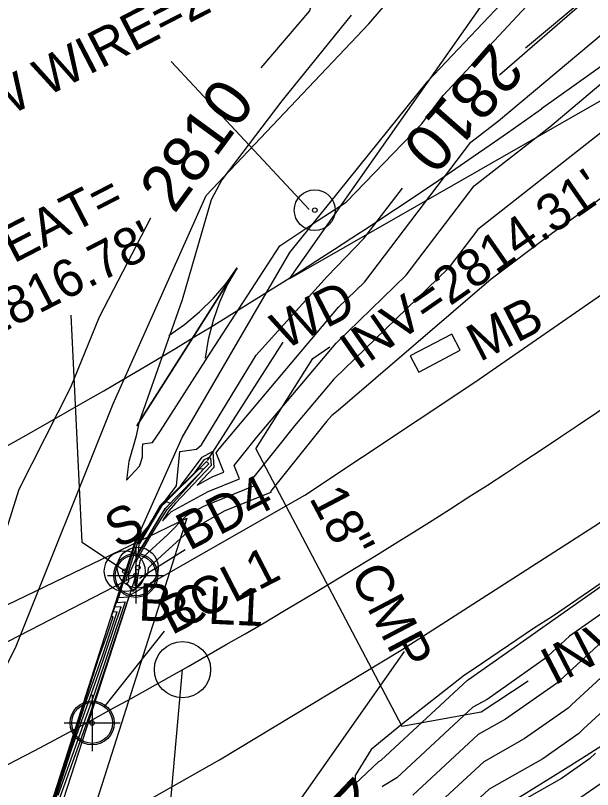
# Model space of a CAD drawing. Extents: x 1284446 to 1285480, y 969739 to 970628.
# Drawn here: x 1284903.3 to 1284964.9, y 970190.8 to 970273.5 of the extents above; entities that cross this region are included whole.
import ezdxf

# ---------------------------------------------------------------- set-up
doc = ezdxf.new("R2010")
doc.units = 0
for name, color, linetype in [('Cogo Default Point CELL', 7, 'Continuous'), ('Default', 7, 'Continuous'), ('Exist Horizontal Alignment', 7, 'Continuous'), ('Exist Horizontal Alignment Point', 7, 'Continuous'), ('Exist Hydro Jurisdictional Stream or Body of Water', 7, 'Continuous'), ('Exist Hydro River Flow Arrow CELL', 7, 'Continuous'), ('Exist Other Culture Fence Line', 7, 'Continuous'), ('Exist Other Culture Located Object CELL', 7, 'Continuous'), ('Exist Other Culture Located Object Leader', 7, 'Continuous'), ('Exist Other Culture Located Object Text', 7, 'Continuous'), ('Exist Other Culture Sign CELL', 7, 'Continuous'), ('Exist Other Culture Sign Text', 7, 'Continuous'), ('Exist Right of Way Line', 7, 'Continuous'), ('Exist Roads EOP', 7, 'Continuous'), ('Exist Roads Soil', 7, 'Continuous'), ('Exist Structure Major Bridge WW', 7, 'Continuous'), ('Exist Structure Major Bridge WW Leader', 7, 'Continuous'), ('Exist Structure Major Bridge WW Text', 7, 'Continuous'), ('Exist Structure Major Deck Tunnel Box Culvert', 7, 'Continuous'), ('Exist Structure Minor Head and End Wall', 7, 'Continuous'), ('Exist Structure Minor Pipes CMP 18 Inch', 7, 'Continuous'), ('Exist Structure Minor Pipes CMP 18 Inch Invert', 7, 'Continuous'), ('Exist Structure Minor Pipes CMP 18 Inch Leader', 7, 'Continuous'), ('Exist Structure Minor Pipes CMP 18 Inch Text', 7, 'Continuous'), ('Exist Utilities Other Located Object CELL', 7, 'Continuous'), ('Exist Utilities Other Located Object Leader', 7, 'Continuous'), ('Exist Utilities Other Located Object Text', 7, 'Continuous'), ('Exist Vegetation Woods Line', 7, 'Continuous')]:
    doc.layers.add(name, color=color, linetype=linetype)

msp = doc.modelspace()

# ---------------------------------------------------------------- linework, layer by layer
at = {"layer": 'Cogo Default Point CELL'}
for points in [[(1284916.141, 970216.687), (1284916.141, 970213.687)], [(1284913.141, 970213.687), (1284916.141, 970213.687)], [(1284916.141, 970213.687), (1284919.141, 970213.687)], [(1284916.141, 970213.687), (1284916.141, 970210.687)], [(1284911.49, 970200.942), (1284911.49, 970197.942)], [(1284908.49, 970197.942), (1284911.49, 970197.942)], [(1284911.49, 970197.942), (1284914.49, 970197.942)], [(1284911.49, 970197.942), (1284911.49, 970194.942)]]:
    msp.add_lwpolyline(points, dxfattribs=at)
for centre in [(1284916.141, 970213.687), (1284911.49, 970197.942)]:
    msp.add_circle(centre, 2.344, dxfattribs=at)
at = {"layer": 'Default'}
for points in [[(1284993.353, 970338.772), (1284991.968, 970336.215), (1284985.772, 970331.038), (1284969.063, 970325.96), (1284962.853, 970312.438), (1284950.453, 970302.482), (1284943.379, 970292.882), (1284936.842, 970279.392), (1284935.155, 970275.904), (1284934.659, 970273.982), (1284929.481, 970267.886)], [(1284957.725, 970270.027), (1284971.01, 970281.137), (1284973.097, 970282.91), (1284979.044, 970288.111), (1284991.312, 970298.925), (1284992.311, 970299.757), (1285008.113, 970310.045), (1285009.581, 970311.09), (1285032.275, 970326.549), (1285033.302, 970327.279), (1285034.748, 970328.264), (1285037.251, 970330.357)], [(1284939.112, 970273.487), (1284931.708, 970264.363), (1284925.305, 970255.933), (1284924.194, 970253.801), (1284921.1, 970243.111), (1284916.498, 970230.101), (1284916.136, 970228.435), (1284915.413, 970225.857), (1284915.144, 970223.875), (1284916.55, 970225.358), (1284916.668, 970225.745), (1284916.846, 970226.369), (1284916.854, 970227.25), (1284916.901, 970227.74), (1284917.93, 970227.896), (1284918.794, 970229.142), (1284924.157, 970237.511), (1284931.496, 970248.884), (1284935.562, 970251.582), (1284938.58, 970253.553), (1284946.619, 970261.883), (1284948.946, 970264.937), (1284962.76, 970279.802)], [(1284904.668, 970181.092), (1284910.771, 970200.049), (1284912.626, 970205.215), (1284914.161, 970209.812), (1284913.743, 970209.785), (1284913.903, 970210.31), (1284915.567, 970215.497), (1284916.047, 970217.068), (1284916.143, 970217.509), (1284916.226, 970217.516), (1284916.548, 970217.827), (1284916.563, 970217.649), (1284917.249, 970218.486), (1284918.101, 970219.915), (1284918.819, 970221.161), (1284920.915, 970223.231), (1284923.212, 970226.318), (1284924.322, 970226.921), (1284924.346, 970226.903), (1284924.483, 970225.23), (1284922.697, 970223.343), (1284924.373, 970224.262), (1284925.544, 970224.733), (1284924.704, 970226.792), (1284925.046, 970227.221), (1284937.771, 970242.33), (1284940.54, 970245.015), (1284951.894, 970259.932), (1284954.824, 970262.237), (1284970.86, 970275.722)], [(1284904.949, 970181.621), (1284909.292, 970195.115), (1284912.185, 970203.17), (1284914.578, 970210.338), (1284913.927, 970210.296), (1284914.177, 970211.114), (1284915.353, 970214.779), (1284916.088, 970217.188), (1284916.156, 970217.499), (1284916.285, 970217.51), (1284916.512, 970217.73), (1284916.535, 970217.452), (1284917.008, 970218.03), (1284918.356, 970220.288), (1284918.845, 970221.137), (1284922.469, 970224.715), (1284923.47, 970226.062), (1284923.954, 970226.325), (1284924.125, 970226.198), (1284924.188, 970225.426), (1284920.371, 970221.392), (1284919.658, 970220.602), (1284918.997, 970219.537), (1284919.943, 970220.507), (1284923.875, 970222.664), (1284927.216, 970224.007), (1284926.641, 970225.418), (1284929.054, 970228.438), (1284937.514, 970238.483), (1284944.999, 970245.742), (1284952.253, 970255.273), (1284960.293, 970261.595), (1284970.061, 970269.81)], [(1284965.762, 970260.953), (1284952.612, 970250.613), (1284949.459, 970246.47), (1284937.257, 970234.636), (1284933.061, 970229.654), (1284928.578, 970224.043), (1284928.889, 970223.281), (1284923.377, 970221.067), (1284921.504, 970220.039), (1284919.571, 970218.057), (1284917.465, 970216.134), (1284916.582, 970215.249), (1284916.221, 970212.639), (1284916.118, 970212.512), (1284916.075, 970212.575), (1284916.088, 970212.583), (1284916.17, 970215.104), (1284916.366, 970215.55), (1284917.035, 970216.714), (1284918.009, 970218.333), (1284919.484, 970220.712), (1284923.419, 970225.066), (1284922.952, 970225.04), (1284922.876, 970225.068), (1284918.871, 970221.112), (1284918.611, 970220.661), (1284916.768, 970217.573), (1284916.507, 970217.255), (1284916.476, 970217.632), (1284916.344, 970217.505), (1284916.169, 970217.489), (1284916.129, 970217.308), (1284915.138, 970214.062), (1284914.451, 970211.919), (1284914.111, 970210.807), (1284914.996, 970210.864), (1284911.744, 970201.125), (1284907.814, 970190.18)], [(1284971.031, 970257.751), (1284960.473, 970250.161), (1284954.062, 970245.315), (1284937.743, 970231.297), (1284937.062, 970230.771), (1284936.483, 970230.138), (1284930.515, 970222.668), (1284930.561, 970222.556), (1284925.636, 970220.577), (1284921.706, 970218.352), (1284917.667, 970214.666), (1284917.467, 970214.465), (1284917.385, 970213.872), (1284915.838, 970211.965), (1284915.195, 970212.913), (1284915.39, 970213.028), (1284915.413, 970213.738), (1284916.388, 970215.964), (1284916.527, 970216.205), (1284919.111, 970220.5), (1284919.311, 970220.822), (1284919.844, 970221.411), (1284919.78, 970221.408), (1284919.373, 970221.559), (1284918.896, 970221.088), (1284918.866, 970221.035), (1284916.528, 970217.117), (1284916.479, 970217.057), (1284916.44, 970217.535), (1284916.403, 970217.499), (1284916.182, 970217.48), (1284916.171, 970217.428), (1284914.924, 970213.344), (1284914.724, 970212.723), (1284914.295, 970211.318), (1284915.414, 970211.39), (1284911.304, 970199.08), (1284906.335, 970185.246)], [(1284904.388, 970180.562), (1284912.249, 970204.984), (1284913.067, 970207.26), (1284913.743, 970209.286), (1284913.559, 970209.275), (1284913.63, 970209.506), (1284915.782, 970216.215), (1284916.006, 970216.948), (1284916.13, 970217.518), (1284916.167, 970217.521), (1284916.584, 970217.925), (1284916.591, 970217.846), (1284917.489, 970218.942), (1284917.846, 970219.542), (1284918.793, 970221.185), (1284919.362, 970221.747), (1284920.479, 970223.249), (1284920.834, 970226.907), (1284922.623, 970227.179), (1284923.151, 970227.639), (1284928.991, 970237.213), (1284936.558, 970245.595), (1284940.464, 970249.643), (1284944.58, 970255.046)], [(1284917.725, 970251.824), (1284912.221, 970241.257), (1284909.188, 970233.769), (1284903.658, 970222.875), (1284899.099, 970208.331), (1284895.642, 970208.459), (1284895.374, 970207.464), (1284895.028, 970206.937), (1284895.408, 970206.436), (1284895.414, 970206.433), (1284896.05, 970205.718), (1284895.957, 970205.436), (1284895.886, 970205.226), (1284892.06, 970192.808), (1284892.035, 970192.791), (1284891.792, 970192.037), (1284885.68, 970173.557)], [(1285023.315, 970249.675), (1285021.084, 970248.148), (1285020.161, 970247.565), (1284997.794, 970231.936), (1284995.442, 970230.359), (1284984.499, 970222.715), (1284984.465, 970222.692), (1284962.415, 970207.193), (1284960.098, 970205.059), (1284959.965, 970204.937), (1284953.611, 970200.463), (1284952.107, 970199.612), (1284943.999, 970192.092), (1284942.465, 970191.143), (1284942.427, 970191.107)], [(1285042.653, 970246.7), (1285030.955, 970239.317), (1285026.048, 970235.957), (1285020.076, 970232.189), (1285009.58, 970224.855), (1284995.12, 970215.158), (1284990.095, 970211.647), (1284989.886, 970211.508), (1284979.764, 970204.393), (1284966.442, 970192.123), (1284965.678, 970191.419), (1284963.516, 970189.897), (1284961.431, 970188.717)], [(1284944.414, 970197.709), (1284941.239, 970195.115), (1284939.537, 970192.345), (1284939.507, 970191.4), (1284942.074, 970193.822), (1284942.31, 970193.968), (1284951.534, 970202.522), (1284951.631, 970202.576), (1284958.823, 970207.64), (1284958.83, 970207.646), (1284958.945, 970207.753), (1284982.698, 970224.449), (1284960.581, 970209.292), (1284958.577, 970208.023), (1284952.236, 970203.706), (1284951.208, 970203.06), (1284944.414, 970197.709)], [(1284965.885, 970206.633), (1284961.367, 970202.472), (1284961.108, 970202.233), (1284955.592, 970198.35), (1284952.68, 970196.702), (1284945.687, 970190.217)], [(1284969.355, 970206.073), (1284962.636, 970199.885), (1284962.25, 970199.53), (1284957.573, 970196.237), (1284953.253, 970193.792), (1284947.376, 970188.342), (1284943.247, 970185.786), (1284937.09, 970179.976), (1284936.128, 970177.527), (1284932.242, 970172.962), (1284929.781, 970166.204), (1284927.903, 970162.783), (1284926.325, 970159.414), (1284925.334, 970149.069), (1284927.213, 970144.924), (1284927.837, 970136.625), (1284928.271, 970131.323), (1284934.419, 970108.445), (1284935.987, 970105.544), (1284936.059, 970105.2), (1284928.643, 970101.235)], [(1284972.825, 970205.513), (1284963.905, 970197.298), (1284963.393, 970196.826), (1284959.554, 970194.123), (1284953.826, 970190.882), (1284949.064, 970186.466), (1284943.638, 970183.107), (1284938.697, 970178.445), (1284937.355, 970175.027), (1284934.415, 970171.573), (1284932.553, 970166.46), (1284929.796, 970161.44), (1284927.482, 970156.497), (1284926.953, 970150.975), (1284929.973, 970144.313), (1284930.37, 970139.03), (1284931.171, 970129.256), (1284934.552, 970116.671), (1284940.324, 970105.995), (1284940.368, 970105.785), (1284935.843, 970103.366)], [(1284965.173, 970194.711), (1284964.535, 970194.123), (1284961.535, 970192.01), (1284954.399, 970187.972), (1284950.753, 970184.591), (1284944.029, 970180.429), (1284940.304, 970176.914), (1284938.581, 970172.527), (1284936.587, 970170.184), (1284935.324, 970166.717), (1284931.69, 970160.098), (1284928.638, 970153.581), (1284928.571, 970152.882), (1284932.733, 970143.702), (1284932.903, 970141.436), (1284934.07, 970127.188), (1284934.685, 970124.898), (1284944.661, 970106.446), (1284944.677, 970106.37), (1284943.043, 970105.497)]]:
    msp.add_lwpolyline(points, dxfattribs=at)
at = {"layer": 'Exist Horizontal Alignment'}
msp.add_line((1284917.711, 970165.4), (1284921.129, 970203.635), dxfattribs=at)
msp.add_arc((1284607.883, 970757.202), 636.05, 292.002785, 305.452776, dxfattribs=at)
at = {"layer": 'Exist Horizontal Alignment Point'}
msp.add_circle((1284921.13, 970203.634), 3, dxfattribs=at)
at = {"layer": 'Exist Hydro Jurisdictional Stream or Body of Water'}
for points in [[(1284873.191, 970156.896), (1284883.514, 970166.483), (1284889.938, 970172.965), (1284895.436, 970190.434), (1284903.301, 970205.953), (1284913.733, 970232.003), (1284923.66, 970254.249), (1284941.007, 970272.574), (1284958.155, 970292.526), (1284979.255, 970313.173), (1284998.608, 970327.405), (1285021.767, 970343.415), (1285038.635, 970357.962), (1285060.694, 970382.427), (1285077.066, 970403.68), (1285083.989, 970417.362), (1285093.674, 970433.198), (1285120.383, 970455.771)], [(1284898.552, 970093.674), (1284891.925, 970104.571), (1284887.089, 970113.682), (1284882.059, 970129.577), (1284887.805, 970135.613), (1284894.463, 970156.081), (1284893.685, 970164.507), (1284897.372, 970171.054), (1284903.86, 970179.349), (1284904.341, 970180.602), (1284915.977, 970216.964), (1284921.108, 970228.406), (1284932.561, 970248.168), (1284947.309, 970266.45), (1284964.912, 970285.055), (1284987.353, 970303.198), (1285005.056, 970315.298), (1285028.92, 970334.487), (1285047.82, 970349.987), (1285069.692, 970374.615), (1285084.308, 970397.98), (1285093.11, 970411.535), (1285103.272, 970427.017), (1285126.728, 970448.135)]]:
    msp.add_lwpolyline(points, dxfattribs=at)
at = {"layer": 'Exist Hydro River Flow Arrow CELL'}
msp.add_line((1284921.602, 970238.095), (1284921.602, 970238.095), dxfattribs=at)
msp.add_lwpolyline([(1284919.669, 970239.318), (1284921.344, 970240.492), (1284922.939, 970241.82), (1284924.43, 970243.288), (1284925.79, 970244.853), (1284926.95, 970246.545), (1284916.254, 970229.645), (1284926.95, 970246.545), (1284925.917, 970244.772), (1284925.085, 970242.873), (1284924.397, 970240.897), (1284923.879, 970238.888), (1284923.535, 970236.872)], dxfattribs=at)
at = {"layer": 'Exist Other Culture Fence Line'}
msp.add_lwpolyline([(1285182.442, 970426.985), (1285127.532, 970386.926), (1285081.552, 970356.809), (1285037.111, 970332.557), (1285005.278, 970312.728), (1284979.015, 970288.014), (1284954.934, 970267.092)], dxfattribs=at)
at = {"layer": 'Exist Other Culture Located Object CELL'}
msp.add_lwpolyline([(1284946.328, 970235.396), (1284950.751, 970237.73), (1284949.84, 970239.456), (1284945.417, 970237.122)], close=True, dxfattribs=at)
for centre, radius in [((1284914.967, 970214.139), 2.18), ((1284916.141, 970213.687), 2.18), ((1284914.967, 970214.139), 0.24), ((1284916.141, 970213.687), 0.24), ((1284911.49, 970197.942), 2.18), ((1284911.49, 970197.942), 0.24)]:
    msp.add_circle(centre, radius, dxfattribs=at)
at = {"layer": 'Exist Other Culture Located Object Leader'}
for p, q in [((1284916.543, 970213.402), (1284921.405, 970216.473)), ((1284912.774, 970199.638), (1284919.218, 970207.744))]:
    msp.add_line(p, q, dxfattribs=at)
msp.add_lwpolyline([(1284914.967, 970214.139), (1284910.418, 970217.198), (1284909.254, 970241.471)], dxfattribs=at)
at = {"layer": 'Exist Other Culture Located Object Text'}
for p, q in [((1284864.825, 970192.389), (1284921.603, 970219.816)), ((1284921.603, 970219.816), (1284909.054, 970180.437))]:
    msp.add_line(p, q, dxfattribs=at)
at = {"layer": 'Exist Other Culture Sign CELL'}
for radius in [2.18, 0.24]:
    msp.add_circle((1284916.356, 970214.523), radius, dxfattribs=at)
at = {"layer": 'Exist Right of Way Line'}
msp.add_line((1285172.162, 970415.007), (1284959.411, 970263.517), dxfattribs=at)
for radius in [606.05, 666.05]:
    msp.add_arc((1284607.883, 970757.202), radius, 292.002785, 305.452776, dxfattribs=at)
at = {"layer": 'Exist Roads EOP'}
for points in [[(1284915.494, 970211.588), (1284915.697, 970211.691), (1284934.182, 970222.248), (1284952.291, 970234.314), (1284978.036, 970252.145), (1285001.962, 970268.988), (1285024.008, 970284.75), (1285046.433, 970300.937), (1285068.794, 970317.003), (1285091.504, 970333.21), (1285113.877, 970349.184), (1285137.455, 970366.054), (1285160.856, 970382.777), (1285183.611, 970398.866)], [(1284906.416, 970183.309), (1284909.887, 970185.394), (1284925.086, 970193.996), (1284944.45, 970205.721), (1284965.49, 970219.252), (1284989.098, 970235.634), (1285013.023, 970252.465), (1285035.596, 970268.522), (1285058.253, 970284.751), (1285080.338, 970300.375), (1285103.047, 970316.584), (1285125.598, 970332.829), (1285149.347, 970349.654), (1285172.355, 970366.089), (1285195.515, 970382.272)]]:
    msp.add_lwpolyline(points, dxfattribs=at)
at = {"layer": 'Exist Roads Soil'}
msp.add_lwpolyline([(1284944.788, 970205.561), (1284933.598, 970189.665), (1284927.061, 970176.274), (1284923.85, 970165.655), (1284922.668, 970145.93), (1284924.834, 970133.774), (1284934.499, 970104.988)], dxfattribs=at)
at = {"layer": 'Exist Structure Major Bridge WW'}
msp.add_lwpolyline([(1284923.936, 970225.594), (1284923.67, 970225.863), (1284918.9, 970221.085), (1284916.473, 970217.012), (1284916.394, 970216.072), (1284919.284, 970220.839), (1284923.936, 970225.594)], dxfattribs=at)
at = {"layer": 'Exist Structure Major Bridge WW Leader'}
msp.add_line((1284923.802, 970225.972), (1284931.862, 970238.586), dxfattribs=at)
at = {"layer": 'Exist Structure Major Deck Tunnel Box Culvert'}
msp.add_lwpolyline([(1284893.517, 970202.025), (1284916.141, 970213.687), (1284905.121, 970179.642), (1284882.421, 970167.887), (1284893.517, 970202.025)], dxfattribs=at)
at = {"layer": 'Exist Structure Minor Head and End Wall'}
for points in [[(1284916.426, 970217.497), (1284916.187, 970217.476), (1284914.838, 970213.059)], [(1284915.12, 970213.217), (1284916.426, 970217.497)]]:
    msp.add_lwpolyline(points, dxfattribs=at)
at = {"layer": 'Exist Structure Minor Pipes CMP 18 Inch'}
msp.add_line((1284928.934, 970227.194), (1284944.528, 970197.608), dxfattribs=at)
at = {"layer": 'Exist Structure Minor Pipes CMP 18 Inch Leader'}
for points in [[(1284928.934, 970227.194), (1284935.04, 970236.844), (1284936.826, 970238.087)], [(1284944.528, 970197.608), (1284952.994, 970199.122), (1284957.986, 970202.451)]]:
    msp.add_lwpolyline(points, dxfattribs=at)
at = {"layer": 'Exist Utilities Other Located Object CELL'}
for radius in [2.18, 0.24]:
    msp.add_circle((1284935.235, 970252.685), radius, dxfattribs=at)
at = {"layer": 'Exist Utilities Other Located Object Leader'}
msp.add_line((1284934.651, 970252.758), (1284919.93, 970268.563), dxfattribs=at)
at = {"layer": 'Exist Vegetation Woods Line'}
msp.add_lwpolyline([(1285171.523, 970440.57), (1285121.644, 970393.923), (1285081.626, 970356.869), (1285045.468, 970320.171), (1285013.496, 970297.408), (1284993.359, 970280.224), (1284932.548, 970245.359), (1284996.184, 970336.002), (1285054.451, 970386.33), (1285100.519, 970417.686), (1285131.323, 970449.808)], dxfattribs=at)

# ---------------------------------------------------------------- texts
at = {"layer": 'Default'}
for s, rotation, p in [('2810', 228.73317, (1284954.122, 970270.761)), ('2810', 53.79956, (1284920.261, 970252.196)), ('2820', 226.42269, (1284939.516, 970192.456))]:
    msp.add_text(s, height=5, rotation=rotation, dxfattribs=at).set_placement(p)
at = {"layer": 'Exist Other Culture Located Object Text'}
for s, rotation, p in [('SEAT=', 27.32349, (1284899.945, 970245.325)), ("2816.78'", 27.32349, (1284900.517, 970238.866)), ('MB', 27.32349, (1284952.824, 970236.439)), ('BD4', 27.32349, (1284921.836, 970216.274)), ('BCL1', 27.32349, (1284919.973, 970207.279)), ('BCL1', 357.32349, (1284916.364, 970208.894))]:
    msp.add_text(s, height=4, rotation=rotation, dxfattribs=at).set_placement(p)
at = {"layer": 'Exist Other Culture Sign Text'}
msp.add_text('S', height=4, rotation=27.32349, dxfattribs=at).set_placement((1284914.19, 970216.48))
at = {"layer": 'Exist Structure Major Bridge WW Text'}
msp.add_text('WD', height=4, rotation=27.32349, dxfattribs=at).set_placement((1284931.983, 970237.718))
at = {"layer": 'Exist Structure Minor Pipes CMP 18 Inch Invert'}
for s, rotation, p in [("INV=2814.31'", 34.8371, (1284939.773, 970235.524)), ("INV=2815.83'", 27.32349, (1284960.759, 970201.897))]:
    msp.add_text(s, height=4, rotation=rotation, dxfattribs=at).set_placement(p)
at = {"layer": 'Exist Structure Minor Pipes CMP 18 Inch Text'}
msp.add_text('18" CMP', height=4, rotation=297.79253, dxfattribs=at).set_placement((1284934.587, 970221.958))
at = {"layer": 'Exist Utilities Other Located Object Text'}
msp.add_text("LOW WIRE=2833.21'", height=4, rotation=27.32349, dxfattribs=at).set_placement((1284894.473, 970258.484))

doc.saveas('drawing.dxf')
